(* Logix 5000 project; controller ControlNetRouterExample_R03 vendor 1 type 14 code 96 rev 19.11; software revision 19.01 *)

TASK MainTask (continuous, watchdog 500 ms) : MainProgram

MODULES
   Local : vendor 1 type 14 code 96 (ICP 0, rev 19.11)
      CnetBridge : vendor 1 type 12 code 8 (ICP 1, rev 11.1)
         CNR01 : vendor 1 type 0 code 16 (ControlNet 2, rev 1.1, Output RPI 20 ms)
      EnetBridge : vendor 1 type 12 code 200 (ICP 2, rev 11.1)
         eCNR01 : ETHERNET-MODULE (Ethernet 192.168.1.166, rev 1.1, Output RPI 100 ms)
END_MODULES

TYPE AparianCNREInput :
STRUCT
   GeneralStatus : SINT;
   CNetNodeNumber : SINT;
   CNetLedState : SINT;
   CNetMode : SINT;
   Temperature : REAL;
   MappedData : SINT[492];
END_STRUCT
END_TYPE

TYPE AparianCNREOutput :
STRUCT
   GeneralCtrl : DINT;
   MappedData : SINT[492];
END_STRUCT
END_TYPE

TYPE AparianCNRInput :
STRUCT
   GeneralStatus : SINT;
   CNetNodeNumber : SINT;
   CNetLedState : SINT;
   CNetMode : SINT;
   Temperature : REAL;
   MappedData : SINT[400];
END_STRUCT
END_TYPE

TYPE AparianCNROutput :
STRUCT
   GeneralCtrl : DINT;
   MappedData : SINT[400];
END_STRUCT
END_TYPE

VAR_GLOBAL   (* controller tags *)
   CNR01Input : AparianCNRInput;
   CNR01Output : AparianCNROutput;
   eCNR01Input1 : AparianCNREInput;
   eCNR01Output1 : AparianCNREOutput;
END_VAR

PROGRAM MainProgram   (* main routine MainRoutine *)

ROUTINE ControlNetRouter   (* ladder *)
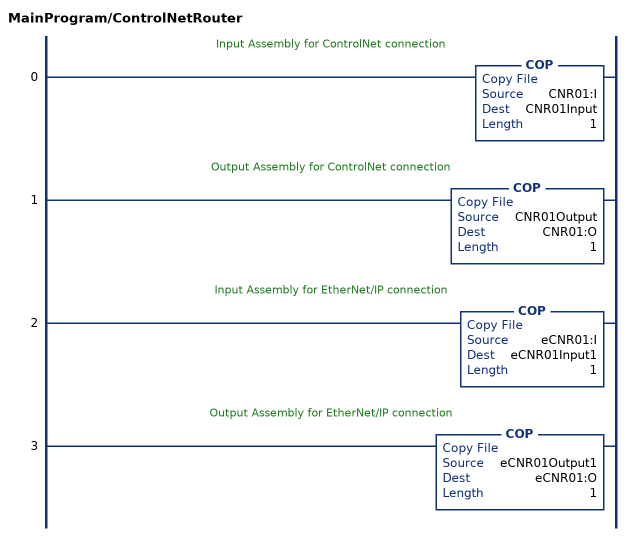
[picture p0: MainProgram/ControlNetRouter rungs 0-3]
   // Input Assembly for ControlNet connection
   0: COP(CNR01:I,CNR01Input,1);
   // Output Assembly for ControlNet connection
   1: COP(CNR01Output,CNR01:O,1);
   // Input Assembly for EtherNet/IP connection
   2: COP(eCNR01:I,eCNR01Input1,1);
   // Output Assembly for EtherNet/IP connection
   3: COP(eCNR01Output1,eCNR01:O,1);
END_ROUTINE

ROUTINE MainRoutine   (* ladder *)
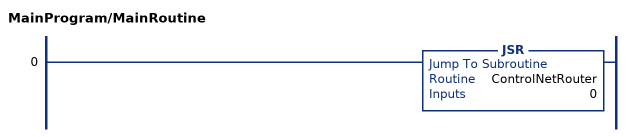
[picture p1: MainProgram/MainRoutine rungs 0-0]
   0: JSR(ControlNetRouter,0);
END_ROUTINE
END_PROGRAM
